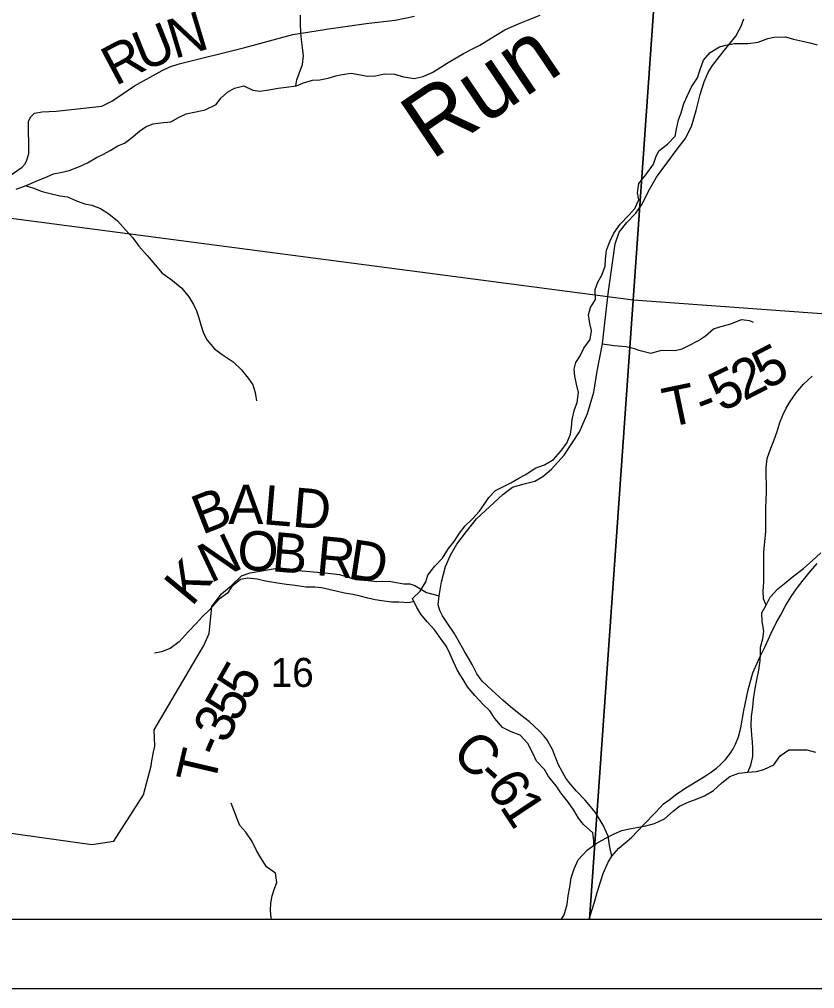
# Model space of a CAD drawing. Extents: x 0 to 40.8, y 0 to 22.
# Drawn here: x 4.37 to 5.517, y 14 to 15.397 of the extents above; entities that cross this region are included whole.
import ezdxf

# ---------------------------------------------------------------- set-up
doc = ezdxf.new("R2010")
doc.units = 0
for name, color, linetype in [('Default', 7, 'Continuous'), ('GM_X_County_Road', 7, 'Continuous'), ('GM_X_County_Road_Text', 7, 'Continuous'), ('GM_X_Minor_River', 7, 'Continuous'), ('GM_X_Minor_River_Text', 7, 'Continuous'), ('GM_X_Section', 7, 'Continuous'), ('GM_X_Section_Text', 7, 'Continuous'), ('GM_X_Township_Road', 7, 'Continuous'), ('GM_X_Township_Road_Text', 7, 'Continuous'), ('SH_Cut_Line', 7, 'Continuous'), ('SH_Data', 7, 'Continuous')]:
    doc.layers.add(name, color=color, linetype=linetype)

msp = doc.modelspace()

# ---------------------------------------------------------------- linework, layer by layer
at = {"layer": 'Default'}
msp.add_lwpolyline([(2.1, 16.4387), (2.1, 14.1), (8.9, 14.1), (8.9, 16.9831), (7.7161, 17.0658), (7.7144, 17.066), (7.54, 17.0745), (7.4495, 17.0841), (6.9172, 17.1197), (6.1785, 17.166), (5.6278, 17.197), (5.3407, 17.2146), (4.8294, 17.2493), (4.5348, 17.2687), (3.4481, 17.3334), (3.1244, 17.3534), (2.8484, 17.3691), (2.8463, 17.3693), (2.4594, 17.3966), (2.4379, 17.0913), (2.3911, 16.4258)], close=True, dxfattribs=at)
at = {"layer": 'GM_X_County_Road'}
for points in [[(5.2246, 14.191), (5.2214, 14.2039), (5.2192, 14.2196), (5.212, 14.2356), (5.2011, 14.2537), (5.186, 14.2717), (5.1734, 14.2849), (5.1627, 14.2977), (5.158, 14.3036), (5.1534, 14.312), (5.147, 14.3234), (5.1392, 14.3449), (5.1307, 14.359), (5.1267, 14.3644), (5.1197, 14.3719), (5.1056, 14.3847), (5.0935, 14.3942), (5.0784, 14.4065), (5.0672, 14.4161), (5.0516, 14.4301), (5.0376, 14.4435), (5.0299, 14.4537), (5.0231, 14.4673), (5.0112, 14.4878), (4.9972, 14.5123), (4.9871, 14.5274), (4.9803, 14.5375), (4.9764, 14.5452), (4.9741, 14.5533), (4.9757, 14.5663), (4.9791, 14.5867), (4.9847, 14.6088), (4.9917, 14.625), (5.0012, 14.641), (5.0149, 14.6591), (5.0294, 14.6775), (5.0675, 14.7126), (5.0813, 14.7231), (5.0962, 14.7275), (5.1137, 14.7318), (5.1252, 14.7384), (5.1375, 14.7489), (5.1556, 14.769), (5.1781, 14.8029), (5.1893, 14.8291), (5.1984, 14.8599), (5.2034, 14.8905), (5.2112, 14.9296), (5.2145, 14.9598), (5.2198, 15.0056), (5.2264, 15.0531), (5.2293, 15.074), (5.2353, 15.0907), (5.2462, 15.1044), (5.259, 15.1183), (5.2685, 15.1319), (5.2774, 15.1499), (5.2891, 15.1698), (5.304, 15.1904), (5.3185, 15.2106), (5.3302, 15.2254), (5.3396, 15.243), (5.3459, 15.2661), (5.3521, 15.2894), (5.3575, 15.3076), (5.3633, 15.3208), (5.3695, 15.3311), (5.3798, 15.3441), (5.389, 15.3556), (5.4034, 15.3734), (5.4082, 15.3824), (5.4108, 15.3879), (5.4148, 15.3982)], [(5.2246, 14.191), (5.2348, 14.2024), (5.2528, 14.2181), (5.2702, 14.236), (5.2879, 14.2542), (5.2991, 14.2662), (5.3065, 14.2718), (5.3182, 14.281), (5.3335, 14.2911), (5.3518, 14.3021), (5.3596, 14.3069), (5.367, 14.3117), (5.3752, 14.3178), (5.3815, 14.3234), (5.3886, 14.3303), (5.3953, 14.3389), (5.3996, 14.3458), (5.4026, 14.3527), (5.407, 14.3631), (5.4103, 14.3758), (5.415, 14.401), (5.4213, 14.4306), (5.428, 14.4553), (5.4377, 14.4778), (5.4456, 14.4933), (5.4543, 14.5124), (5.4616, 14.5276), (5.4682, 14.5391), (5.4749, 14.5518), (5.4833, 14.5655), (5.4909, 14.5765), (5.5003, 14.5887), (5.511, 14.6017), (5.5206, 14.6128)], [(5.1919, 14.1), (5.1959, 14.1128), (5.1994, 14.1248), (5.2035, 14.1385), (5.2088, 14.1553), (5.2121, 14.166), (5.2192, 14.1822), (5.2246, 14.191)]]:
    msp.add_lwpolyline(points, dxfattribs=at)
for points in [[(4.1612, 14.1), (5.1921, 14.1), (5.2555, 14.9926), (4.2184, 15.1287)], [(5.1921, 14.1), (6.208, 14.1), (6.2633, 14.9194), (5.2555, 14.9926)]]:
    msp.add_lwpolyline(points, close=True, dxfattribs=at)
at = {"layer": 'GM_X_Minor_River'}
for points in [[(4.7687, 15.3017), (4.7704, 15.3102), (4.7738, 15.3197), (4.7783, 15.3326), (4.7799, 15.3448), (4.7783, 15.3569), (4.7772, 15.3683), (4.7761, 15.3782), (4.7757, 15.3914), (4.7757, 15.4036)], [(4.978, 15.3284), (4.9886, 15.3353), (5, 15.3421), (5.0106, 15.3481), (5.0238, 15.355), (5.0341, 15.3603), (5.0443, 15.3667), (5.0591, 15.3755), (5.0701, 15.3823), (5.0799, 15.3868), (5.0932, 15.3925), (5.103, 15.3963), (5.1212, 15.4035)], [(5.3478, 15.3132), (5.3516, 15.3238), (5.3569, 15.3386), (5.3663, 15.3496), (5.3796, 15.358), (5.3891, 15.3602), (5.4016, 15.3625), (5.4205, 15.3625), (5.4353, 15.3648), (5.4493, 15.3697), (5.4588, 15.372), (5.4747, 15.3724), (5.4864, 15.3689), (5.4993, 15.3663), (5.5107, 15.3636), (5.5205, 15.3606)], [(4.3657, 15.1529), (4.3801, 15.1578), (4.3945, 15.1642), (4.4097, 15.1707), (4.4195, 15.1749), (4.4298, 15.1768), (4.4423, 15.1798), (4.457, 15.1855), (4.4684, 15.1908), (4.4813, 15.1984), (4.4915, 15.2033), (4.5014, 15.2086), (4.5124, 15.2151), (4.5218, 15.2189), (4.5313, 15.2264), (4.5434, 15.2363), (4.5533, 15.2431), (4.5631, 15.2469), (4.5737, 15.2481), (4.5885, 15.25), (4.5995, 15.256), (4.6109, 15.2613), (4.6249, 15.264), (4.6381, 15.267), (4.6541, 15.2746), (4.6609, 15.2841), (4.6704, 15.2924), (4.6806, 15.2985), (4.6938, 15.3015), (4.7067, 15.2955), (4.717, 15.2939), (4.7298, 15.2958), (4.7435, 15.2985), (4.7552, 15.2996), (4.77, 15.3019), (4.7802, 15.3061), (4.7931, 15.3099), (4.8037, 15.3102), (4.8155, 15.3129), (4.8264, 15.3159), (4.8359, 15.3182), (4.8488, 15.3201), (4.8621, 15.3174), (4.8719, 15.3155), (4.884, 15.3159), (4.8969, 15.319), (4.9113, 15.3186), (4.9242, 15.3148), (4.9394, 15.3121), (4.9526, 15.3152), (4.9663, 15.3216), (4.978, 15.3284)], [(5.1986, 14.2071), (5.1987, 14.2132), (5.1972, 14.2246), (5.1839, 14.2364), (5.1764, 14.2459), (5.1695, 14.2573), (5.162, 14.2683), (5.151, 14.2823), (5.1442, 14.2922), (5.1332, 14.3058), (5.1275, 14.3161), (5.1161, 14.3278), (5.1108, 14.3396), (5.1033, 14.3536), (5.0923, 14.3654), (5.0794, 14.3703), (5.0669, 14.3764), (5.0559, 14.3897), (5.0487, 14.4003), (5.0392, 14.4098), (5.0271, 14.4227), (5.0165, 14.4352), (5.0104, 14.4455), (5.0021, 14.4588), (4.9961, 14.4713), (4.9911, 14.4831), (4.9862, 14.4933), (4.976, 14.5073), (4.9695, 14.5168), (4.9582, 14.529), (4.9491, 14.54), (4.9434, 14.5495), (4.9373, 14.5624), (4.9483, 14.573), (4.9563, 14.5863), (4.9593, 14.5961), (4.9688, 14.6087), (4.9802, 14.6208), (4.9889, 14.6345), (4.9972, 14.6447), (5.0048, 14.6565), (5.0131, 14.6675), (5.0234, 14.6773), (5.0336, 14.6883), (5.0404, 14.6978), (5.0472, 14.7081), (5.0567, 14.7183), (5.0666, 14.7232), (5.0791, 14.7293), (5.0904, 14.7358), (5.1007, 14.7414), (5.1139, 14.7502), (5.1272, 14.7551), (5.1404, 14.7627), (5.1503, 14.7744), (5.1598, 14.7866), (5.1651, 14.7995), (5.1666, 14.8097), (5.1674, 14.8207), (5.1708, 14.8348), (5.1746, 14.845), (5.1765, 14.8594), (5.1738, 14.8716), (5.1712, 14.883), (5.17, 14.8932), (5.1727, 14.9027), (5.1787, 14.9126), (5.184, 14.9236), (5.1931, 14.9357), (5.1954, 14.949), (5.1928, 14.9588), (5.1909, 14.9717), (5.1939, 14.982), (5.2011, 14.9937), (5.2003, 15.0082), (5.2041, 15.0184), (5.2102, 15.0287), (5.2147, 15.0416), (5.2155, 15.0518), (5.217, 15.0647), (5.222, 15.078), (5.2276, 15.0894), (5.2367, 15.1023), (5.2492, 15.1152), (5.2576, 15.1246), (5.2633, 15.1375), (5.2617, 15.1474), (5.2636, 15.1611), (5.2735, 15.1732), (5.2845, 15.1888), (5.2879, 15.1986), (5.2924, 15.2081), (5.3046, 15.2176), (5.3159, 15.2293), (5.3178, 15.2392), (5.3205, 15.2525), (5.3243, 15.2627), (5.3284, 15.276), (5.3337, 15.2878), (5.3394, 15.3003), (5.3478, 15.3132)], [(4.38, 15.1577), (4.3896, 15.1544), (4.4032, 15.1494), (4.4146, 15.1464), (4.4286, 15.143), (4.4396, 15.1415), (4.4525, 15.1358), (4.4646, 15.1316), (4.4748, 15.1297), (4.4873, 15.1248), (4.4991, 15.1172), (4.512, 15.1069), (4.5233, 15.094), (4.5339, 15.0826), (4.5426, 15.0705), (4.5548, 15.0572), (4.5661, 15.0436), (4.5764, 15.0318), (4.5885, 15.0227), (4.6044, 15.0098), (4.6146, 14.9976), (4.6214, 14.9866), (4.6256, 14.9771), (4.629, 14.9673), (4.632, 14.957), (4.6358, 14.9453), (4.6411, 14.935), (4.6517, 14.9225), (4.6627, 14.9142), (4.6786, 14.9039), (4.6904, 14.8921), (4.7002, 14.88), (4.7067, 14.8705), (4.7101, 14.8595), (4.7123, 14.8477)], [(5.4468, 14.553), (5.4431, 14.5619), (5.4428, 14.5733), (5.4435, 14.5862), (5.4439, 14.5976), (5.4439, 14.6078), (5.4435, 14.6196), (5.4439, 14.6291), (5.4447, 14.6397), (5.4458, 14.6492), (5.4466, 14.6598), (5.4466, 14.6928), (5.4469, 14.7053), (5.4473, 14.7152), (5.4473, 14.7273), (5.4469, 14.7387), (5.4469, 14.7516), (5.4485, 14.7645), (5.4538, 14.7793), (5.4587, 14.7911), (5.4629, 14.8032), (5.4667, 14.8161), (5.4712, 14.8268), (5.4758, 14.837), (5.4818, 14.8465), (5.4905, 14.859), (5.5008, 14.8715), (5.5133, 14.8833)], [(5.4205, 14.3122), (5.4249, 14.3221), (5.4276, 14.3346), (5.4276, 14.3464), (5.4272, 14.3559), (5.4264, 14.3654), (5.4253, 14.3794), (5.4261, 14.3923), (5.4276, 14.406), (5.4287, 14.4173), (5.4314, 14.4329), (5.4336, 14.445), (5.4363, 14.4591), (5.4386, 14.4727), (5.439, 14.4826), (5.439, 14.4921), (5.4424, 14.5042), (5.4439, 14.5152), (5.4412, 14.5293), (5.4409, 14.5418), (5.4473, 14.5539), (5.4526, 14.5646), (5.464, 14.5763), (5.4734, 14.5839), (5.4871, 14.5953), (5.5007, 14.6059), (5.5144, 14.6177), (5.5257, 14.6283)], [(4.9393, 14.5581), (4.9317, 14.5563), (4.9176, 14.5571), (4.9067, 14.5574), (4.893, 14.559), (4.8835, 14.5605), (4.8729, 14.5628), (4.8616, 14.5658), (4.8513, 14.5681), (4.8392, 14.57), (4.829, 14.5726), (4.8184, 14.5749), (4.8059, 14.5779), (4.7964, 14.5787), (4.7831, 14.5787), (4.768, 14.581), (4.7555, 14.5829), (4.7426, 14.5844), (4.7252, 14.5874), (4.7131, 14.5905), (4.699, 14.592), (4.6892, 14.5897), (4.6767, 14.5799), (4.6706, 14.5704), (4.6585, 14.5613), (4.6445, 14.5461), (4.6339, 14.5359), (4.6252, 14.5264), (4.6138, 14.5142), (4.6005, 14.5002), (4.5876, 14.4903), (4.5751, 14.4854), (4.5653, 14.4835)], [(5.2389, 14.228), (5.2525, 14.2307), (5.2635, 14.233), (5.2734, 14.2349), (5.2859, 14.2383), (5.3006, 14.2447), (5.3128, 14.2557), (5.3222, 14.2629), (5.3355, 14.2694), (5.3453, 14.2728), (5.3582, 14.2781), (5.3711, 14.2857), (5.3832, 14.2967), (5.3946, 14.3058), (5.4075, 14.3107), (5.4204, 14.3122), (5.4329, 14.313), (5.4435, 14.3157), (5.4579, 14.3229), (5.467, 14.3354), (5.4799, 14.3445), (5.4939, 14.3445), (5.5056, 14.3441), (5.5181, 14.3407)], [(4.7339, 14.1), (4.7334, 14.1021), (4.7323, 14.1124), (4.7327, 14.1234), (4.7346, 14.1336), (4.7376, 14.1431), (4.7414, 14.153), (4.7395, 14.1663), (4.7266, 14.1754), (4.7183, 14.1886), (4.7122, 14.1993), (4.7058, 14.2122), (4.6967, 14.2255), (4.688, 14.2353), (4.6842, 14.2448), (4.6804, 14.2547), (4.6759, 14.2672)], [(5.1521, 14.1), (5.1559, 14.1066), (5.1601, 14.1214), (5.1616, 14.1339), (5.1642, 14.1465), (5.1657, 14.1597), (5.1703, 14.1726), (5.176, 14.1855), (5.1889, 14.1996), (5.2017, 14.2094), (5.215, 14.2166), (5.2279, 14.2231), (5.2389, 14.228)]]:
    msp.add_lwpolyline(points, dxfattribs=at)
at = {"layer": 'GM_X_Section'}
msp.add_lwpolyline([(5.3264, 16.0026), (5.2555, 14.9926), (4.2184, 15.1287), (4.2989, 16.1489)], close=True, dxfattribs=at)
msp.add_lwpolyline([(6.3112, 15.6512), (6.2633, 14.9194), (5.2555, 14.9926), (5.3264, 16.0026), (5.5999, 15.9856)], dxfattribs=at)
at = {"layer": 'GM_X_Township_Road'}
for points in [[(4.3462, 15.1646), (4.3743, 15.1842), (4.3785, 15.1891), (4.3812, 15.1945), (4.3838, 15.2039), (4.3837, 15.2505), (4.3866, 15.2571), (4.3923, 15.2623), (4.4034, 15.2642), (4.4232, 15.2651), (4.4893, 15.2725), (4.5038, 15.2796), (4.5361, 15.3015), (4.576, 15.3238), (4.5873, 15.3291), (4.6007, 15.3333), (4.6956, 15.3568), (4.7644, 15.3756), (4.786, 15.3792), (4.8132, 15.3835), (4.8701, 15.3915), (4.912, 15.3965), (4.9401, 15.4019)], [(5.2112, 14.9296), (5.2278, 14.9271), (5.2449, 14.9257), (5.2551, 14.9234), (5.2633, 14.9206), (5.2808, 14.9164), (5.2949, 14.9199), (5.3067, 14.9205), (5.3157, 14.9202), (5.3259, 14.9223), (5.3348, 14.9269), (5.3494, 14.9346), (5.3594, 14.9414), (5.3712, 14.9512), (5.3803, 14.9541), (5.3962, 14.9585), (5.4115, 14.9646), (5.4231, 14.9635), (5.4283, 14.961)], [(4.5615, 14.3282), (4.5636, 14.341), (4.5654, 14.3494), (4.5647, 14.3732), (4.6363, 14.4948), (4.644, 14.512), (4.6477, 14.5508), (4.6616, 14.5694), (4.676, 14.5814), (4.6908, 14.5952), (4.703, 14.5996), (4.739, 14.6056), (4.8112, 14.5997), (4.8317, 14.5969), (4.8549, 14.5901), (4.8725, 14.5885), (4.8859, 14.5872), (4.9033, 14.5875), (4.9248, 14.5838), (4.9335, 14.5836), (4.9405, 14.5814), (4.9573, 14.5712), (4.9757, 14.5663)], [(3.9919, 14.3096), (4.2309, 14.2467), (4.3445, 14.2259), (4.475, 14.2079), (4.5064, 14.2128), (4.5493, 14.2793), (4.5603, 14.3214), (4.5615, 14.3282)]]:
    msp.add_lwpolyline(points, dxfattribs=at)
at = {"layer": 'SH_Cut_Line'}
msp.add_lwpolyline([(2.1, 17.4153), (2.1, 14.1), (8.9, 14.1), (8.9, 16.9831), (7.7161, 17.0658), (7.7144, 17.066), (7.54, 17.0745), (7.4495, 17.0841), (6.9172, 17.1197), (6.1785, 17.166), (5.6278, 17.197), (5.3407, 17.2146), (4.8294, 17.2493), (4.5348, 17.2687), (3.4481, 17.3334), (3.1244, 17.3534), (2.8484, 17.3691), (2.8463, 17.3693), (2.4594, 17.3966)], close=True, dxfattribs=at)
at = {"layer": 'SH_Data'}
for p, q in [((2.1, 14.1), (8.9, 14.1)), ((2, 14), (9, 14))]:
    msp.add_line(p, q, dxfattribs=at)

# ---------------------------------------------------------------- texts
at = {"layer": 'GM_X_County_Road_Text'}
for s, rotation, p in [('C', 316.5926, (4.9914, 14.3365)), ('-', 317.9961, (5.0264, 14.3034)), ('6', 305.7718, (5.0416, 14.2902)), ('1', 303.4447, (5.0617, 14.2623))]:
    msp.add_text(s, height=0.0568, rotation=rotation, dxfattribs=at).set_placement(p)
at = {"layer": 'GM_X_Minor_River_Text'}
msp.add_text('Run', height=0.09469, rotation=33.9969, dxfattribs=at).set_placement((4.9644, 15.1936))
at = {"layer": 'GM_X_Section_Text'}
msp.add_text('16', height=0.04186, rotation=0, dxfattribs=at).set_placement((4.7325, 14.435))
at = {"layer": 'GM_X_Township_Road_Text'}
for s, rotation, p in [('N', 16.754, (4.5938, 15.3403)), ('U', 21.9807, (4.5487, 15.3221)), ('R', 27.9563, (4.5089, 15.3008)), ('5', 27.4232, (5.4466, 14.8629)), ('2', 27.0767, (5.4151, 14.8468)), ('5', 25.8147, (5.3824, 14.8309)), ('T', 11.8394, (5.3049, 14.8088)), ('-', 21.5355, (5.3565, 14.8205)), ('B', 21.4318, (4.6336, 14.6539)), ('A', 359.7887, (4.6715, 14.6699)), ('L', 355.147, (4.7203, 14.6698)), ('D', 355.1481, (4.7626, 14.6662)), ('O', 357.7701, (4.6838, 14.6039)), ('N', 25.229, (4.6456, 14.5841)), ('B', 354.9314, (4.733, 14.602)), ('R', 354.5904, (4.7969, 14.5964)), ('D', 351.33, (4.8425, 14.5921)), ('K', 50.3087, (4.6188, 14.5496)), ('5', 60.2286, (4.7012, 14.4124)), ('5', 60.9439, (4.6843, 14.382)), ('3', 63.5792, (4.6691, 14.3513)), ('-', 66.6938, (4.6602, 14.3306)), ('T', 76.7465, (4.6513, 14.2917))]:
    msp.add_text(s, height=0.0568, rotation=rotation, dxfattribs=at).set_placement(p)

doc.saveas('drawing.dxf')
